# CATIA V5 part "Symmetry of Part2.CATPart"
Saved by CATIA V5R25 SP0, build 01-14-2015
Part number: Symmetry of Part2
Bounding box of the stored display mesh (mm): x -5 to 5, y -10 to 9.915, z -106.824 to 9.932
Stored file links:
  D:\feridun18052022montaj\Symmetry of Part2.CATPart
  D:\feridun18052022montaj\04.CATPart
  D:\feridun18052022montaj\cektirme.CATProduct
  D:\feridun18052022montaj\03.CATPart
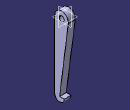
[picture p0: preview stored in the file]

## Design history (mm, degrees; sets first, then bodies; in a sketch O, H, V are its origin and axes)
Body1 (main body)
  Body2 "Body from original PartBody"
    Solid1: linked copy from another document
  Assemble1: tool Body2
